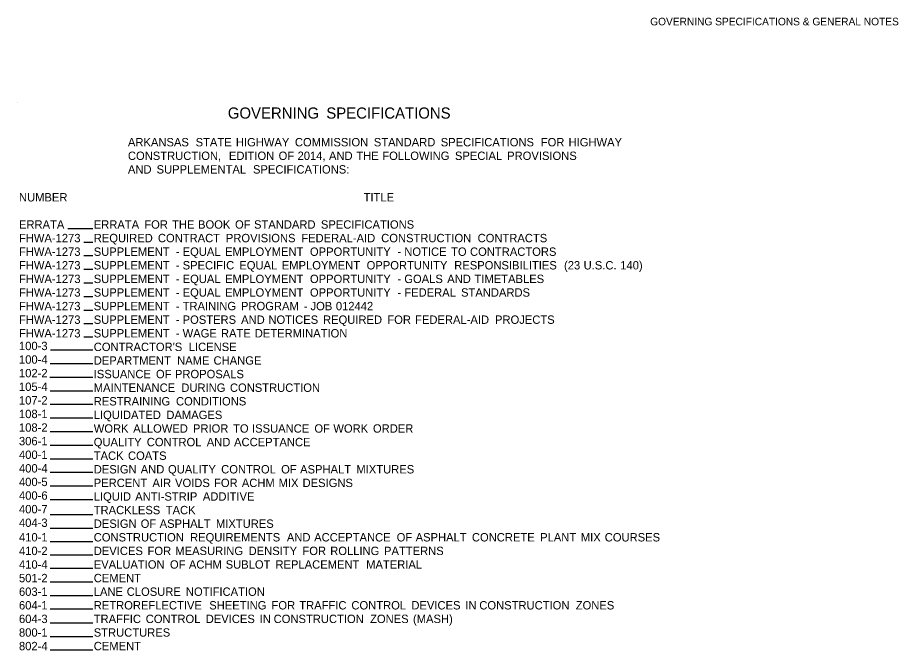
# Model space of a CAD drawing. Extents: x 1930579 to 1932219, y 596452 to 599493.
# Drawn here: x 1931524 to 1932219, y 598994 to 599493 of the extents above; entities that cross this region are included whole.
import ezdxf

# ---------------------------------------------------------------- set-up
doc = ezdxf.new("R2010")
doc.units = 0
for name, color, linetype in [('Default', 7, 'Continuous'), ('R_Border', 7, 'Continuous'), ('R_Border Prem', 7, 'Continuous')]:
    doc.layers.add(name, color=color, linetype=linetype)

msp = doc.modelspace()

# ---------------------------------------------------------------- linework, layer by layer
at = {"layer": 'R_Border'}
for p, q in [((1931524.27, 599426.12), (1931524.27, 599426.12)), ((1931563.85, 599326.81), (1931583.71, 599326.81)), ((1931576.5, 599316.09), (1931583.71, 599316.09)), ((1931576.5, 599305.36), (1931583.71, 599305.36)), ((1931576.5, 599294.64), (1931583.71, 599294.64)), ((1931576.5, 599283.91), (1931583.71, 599283.91)), ((1931576.5, 599273.19), (1931583.71, 599273.19)), ((1931576.5, 599262.46), (1931583.71, 599262.46)), ((1931576.5, 599251.74), (1931583.71, 599251.74)), ((1931576.5, 599241.27), (1931583.53, 599241.27)), ((1931550.12, 599231.03), (1931583.53, 599231.03)), ((1931549.9, 599220.3), (1931583.53, 599220.3)), ((1931549.66, 599209.58), (1931583.53, 599209.58)), ((1931549.9, 599198.85), (1931583.53, 599198.85)), ((1931549.9, 599188.13), (1931583.53, 599188.13)), ((1931549.9, 599177.4), (1931583.53, 599177.4)), ((1931549.9, 599166.68), (1931583.53, 599166.68)), ((1931549.9, 599155.95), (1931583.53, 599155.95)), ((1931549.9, 599145.23), (1931583.53, 599145.23)), ((1931549.9, 599134.5), (1931583.53, 599134.5)), ((1931549.9, 599123.78), (1931583.53, 599123.78)), ((1931549.9, 599113.05), (1931583.53, 599113.05)), ((1931549.9, 599101.16), (1931583.53, 599101.16)), ((1931549.9, 599090.53), (1931583.53, 599090.53)), ((1931549.9, 599079.9), (1931583.53, 599079.9)), ((1931549.9, 599069.37), (1931583.53, 599069.37)), ((1931549.9, 599058.93), (1931583.53, 599058.93)), ((1931549.9, 599048.11), (1931583.53, 599048.11)), ((1931549.9, 599037.2), (1931583.53, 599037.2)), ((1931549.9, 599026.76), (1931583.53, 599026.76)), ((1931549.9, 599015.75), (1931583.53, 599015.75)), ((1931549.9, 599005.12), (1931583.53, 599005.12)), ((1931549.9, 598994.4), (1931583.53, 598994.4))]:
    msp.add_line(p, q, dxfattribs=at)

# ---------------------------------------------------------------- texts
at = {"layer": 'Default'}
for s, height, p in [('GOVERNING', 8.8, (1931690.13, 599413.4)), (' SPECIFICATIONS', 8.8, (1931764.54, 599413.4)), ('           ARKANSAS', 6.6, (1931584.33, 599391.51)), (' STATE', 6.6, (1931662.24, 599391.51)), (' HIGHWAY', 6.6, (1931694.04, 599391.51)), (' COMMISSION', 6.6, (1931740.59, 599391.51)), (' STANDARD', 6.6, (1931802.85, 599391.51)), (' SPECIFICATIONS', 6.6, (1931855.65, 599391.51)), (' FOR', 6.6, (1931934.59, 599391.51)), (' HIGHWAY', 6.6, (1931956.5, 599391.51)), ('           CONSTRUCTION,', 6.6, (1931584.33, 599380.79)), (' EDITION', 6.6, (1931688.52, 599380.79)), (' OF', 6.6, (1931727.73, 599380.79)), (' 2014,', 6.6, (1931742.68, 599380.79)), (' AND', 6.6, (1931767.48, 599380.79)), (' THE', 6.6, (1931789.02, 599380.79)), (' FOLLOWING', 6.6, (1931809.54, 599380.79)), (' SPECIAL', 6.6, (1931866.85, 599380.79)), (' PROVISIONS', 6.6, (1931908.04, 599380.79)), ('           AND', 6.6, (1931584.33, 599370.06)), (' SUPPLEMENTAL', 6.6, (1931631.47, 599370.06)), (' SPECIFICATIONS:', 6.6, (1931707.51, 599370.06)), ('NUMBER', 6.6, (1931525.34, 599348.07)), ('TITLE', 6.6, (1931797.24, 599348.07)), ('ERRATA', 6.6, (1931525.34, 599326.62)), ('ERRATA', 6.6, (1931584.33, 599326.62)), (' FOR', 6.6, (1931621.75, 599326.62)), (' THE', 6.6, (1931643.66, 599326.62)), (' BOOK', 6.6, (1931664.17, 599326.62)), (' OF', 6.6, (1931693.36, 599326.62)), (' STANDARD', 6.6, (1931708.31, 599326.62)), (' SPECIFICATIONS', 6.6, (1931761.11, 599326.62)), ('FHWA-1273', 6.6, (1931525.34, 599315.9)), ('REQUIRED', 6.6, (1931584.33, 599315.9)), (' CONTRACT', 6.6, (1931632.51, 599315.9)), (' PROVISIONS', 6.6, (1931686.12, 599315.9)), (' FEDERAL-AID', 6.6, (1931745.6, 599315.9)), (' CONSTRUCTION', 6.6, (1931808.65, 599315.9)), (' CONTRACTS', 6.6, (1931884.74, 599315.9)), ('FHWA-1273', 6.6, (1931525.34, 599305.17)), ('SUPPLEMENT', 6.6, (1931584.33, 599305.17)), (' EQUAL', 6.6, (1931652.01, 599305.17)), (' EMPLOYMENT', 6.6, (1931685.51, 599305.17)), (' OPPORTUNITY', 6.6, (1931752.45, 599305.17)), (' NOTICE', 6.6, (1931826.89, 599305.17)), (' TO', 6.6, (1931863.8, 599305.17)), (' CONTRACTORS', 6.6, (1931878.76, 599305.17)), (' -', 6.6, (1931646.66, 599305.17)), (' -', 6.6, (1931821.55, 599305.17)), ('FHWA-1273', 6.6, (1931525.34, 599294.45)), ('SUPPLEMENT', 6.6, (1931584.33, 599294.45)), (' -', 6.6, (1931646.66, 599294.45)), (' SPECIFIC', 6.6, (1931652.01, 599294.45)), (' EQUAL', 6.6, (1931696.73, 599294.45)), (' EMPLOYMENT', 6.6, (1931730.23, 599294.45)), (' OPPORTUNITY', 6.6, (1931797.17, 599294.45)), (' RESPONSIBILITIES', 6.6, (1931866.28, 599294.45)), (' (23', 6.6, (1931952.92, 599294.45)), (' U.S.C.', 6.6, (1931968.38, 599294.45)), (' 140)', 6.6, (1931997.29, 599294.45)), ('FHWA-1273', 6.6, (1931525.34, 599283.72)), ('SUPPLEMENT', 6.6, (1931584.33, 599283.72)), (' EQUAL', 6.6, (1931652.01, 599283.72)), (' EMPLOYMENT', 6.6, (1931685.51, 599283.72)), (' OPPORTUNITY', 6.6, (1931752.45, 599283.72)), (' GOALS', 6.6, (1931826.89, 599283.72)), (' AND', 6.6, (1931860.75, 599283.72)), (' TIMETABLES', 6.6, (1931882.29, 599283.72)), (' -', 6.6, (1931646.66, 599283.72)), (' -', 6.6, (1931821.55, 599283.72)), ('FHWA-1273', 6.6, (1931525.34, 599273)), ('SUPPLEMENT', 6.6, (1931584.33, 599273)), (' -', 6.6, (1931646.66, 599273)), (' EQUAL', 6.6, (1931652.01, 599273)), (' EMPLOYMENT', 6.6, (1931685.51, 599273)), (' OPPORTUNITY', 6.6, (1931752.45, 599273)), (' -', 6.6, (1931821.55, 599273)), (' FEDERAL', 6.6, (1931826.89, 599273)), (' STANDARDS', 6.6, (1931871.66, 599273)), ('FHWA-1273', 6.6, (1931525.34, 599262.27)), ('SUPPLEMENT', 6.6, (1931584.33, 599262.27)), (' TRAINING', 6.6, (1931652.01, 599262.27)), (' PROGRAM', 6.6, (1931698.05, 599262.27)), (' JOB', 6.6, (1931752.91, 599262.27)), (' 012442', 6.6, (1931772.92, 599262.27)), (' -', 6.6, (1931646.66, 599262.27)), (' -', 6.6, (1931747.57, 599262.27)), ('FHWA-1273', 6.6, (1931525.34, 599251.55)), ('SUPPLEMENT', 6.6, (1931584.33, 599251.55)), (' -', 6.6, (1931646.66, 599251.55)), (' POSTERS', 6.6, (1931652.01, 599251.55)), (' AND', 6.6, (1931698.16, 599251.55)), (' NOTICES', 6.6, (1931719.7, 599251.55)), (' REQUIRED', 6.6, (1931762.77, 599251.55)), (' FOR', 6.6, (1931813.52, 599251.55)), (' FEDERAL-AID', 6.6, (1931835.42, 599251.55)), (' PROJECTS', 6.6, (1931898.47, 599251.55)), ('FHWA-1273', 6.6, (1931525.34, 599240.82)), ('SUPPLEMENT', 6.6, (1931584.33, 599240.82)), (' WAGE', 6.6, (1931652.01, 599240.82)), (' RATE', 6.6, (1931682.26, 599240.82)), (' DETERMINATION', 6.6, (1931708.92, 599240.82)), (' -', 6.6, (1931646.66, 599240.82)), ('100-3', 6.6, (1931525.34, 599230.84)), ("CONTRACTOR'S", 6.6, (1931584.33, 599230.1)), (' LICENSE', 6.6, (1931656.83, 599230.1)), ('100-4', 6.6, (1931525.34, 599220.12)), ('DEPARTMENT', 6.6, (1931584.33, 599219.37)), (' NAME', 6.6, (1931647.68, 599219.37)), (' CHANGE', 6.6, (1931676.39, 599219.37)), ('102-2', 6.6, (1931525.34, 599209.39)), ('ISSUANCE', 6.6, (1931584.33, 599208.65)), (' OF', 6.6, (1931630.98, 599208.65)), (' PROPOSALS', 6.6, (1931645.93, 599208.65)), ('105-4', 6.6, (1931525.34, 599198.67)), ('MAINTENANCE', 6.6, (1931584.33, 599197.92)), (' DURING', 6.6, (1931650.96, 599197.92)), (' CONSTRUCTION', 6.6, (1931689.32, 599197.92)), ('107-2', 6.6, (1931525.34, 599187.94)), ('RESTRAINING', 6.6, (1931584.33, 599187.2)), (' CONDITIONS', 6.6, (1931646.78, 599187.2)), ('108-1', 6.6, (1931525.34, 599177.22)), ('LIQUIDATED', 6.6, (1931584.33, 599176.47)), (' DAMAGES', 6.6, (1931639.17, 599176.47)), ('108-2', 6.6, (1931525.34, 599166.49)), ('WORK', 6.6, (1931584.33, 599165.75)), (' ALLOWED', 6.6, (1931613, 599165.75)), (' PRIOR', 6.6, (1931660.16, 599165.75)), (' TO', 6.6, (1931691.8, 599165.75)), (' ISSUANCE', 6.6, (1931706.75, 599165.75)), (' OF', 6.6, (1931755.97, 599165.75)), (' WORK', 6.6, (1931770.92, 599165.75)), (' ORDER', 6.6, (1931802.15, 599165.75)), ('306-1', 6.6, (1931525.34, 599155.77)), ('QUALITY', 6.6, (1931584.33, 599155.02)), (' CONTROL', 6.6, (1931623.72, 599155.02)), (' AND', 6.6, (1931671.04, 599155.02)), (' ACCEPTANCE', 6.6, (1931692.58, 599155.02)), ('400-1', 6.6, (1931525.34, 599145.04)), ('TACK', 6.6, (1931584.33, 599144.3)), (' COATS', 6.6, (1931608.91, 599144.3)), ('400-4', 6.6, (1931525.34, 599134.32)), ('DESIGN', 6.6, (1931584.33, 599133.57)), (' AND', 6.6, (1931618.93, 599133.57)), (' QUALITY', 6.6, (1931640.47, 599133.57)), (' CONTROL', 6.6, (1931682.42, 599133.57)), (' OF', 6.6, (1931729.74, 599133.57)), (' ASPHALT', 6.6, (1931744.69, 599133.57)), (' MIXTURES', 6.6, (1931789.09, 599133.57)), ('400-5', 6.6, (1931525.34, 599123.59)), ('PERCENT', 6.6, (1931584.33, 599122.85)), (' AIR', 6.6, (1931628.21, 599122.85)), (' VOIDS', 6.6, (1931646.02, 599122.85)), (' FOR', 6.6, (1931676.8, 599122.85)), (' ACHM', 6.6, (1931698.7, 599122.85)), (' MIX', 6.6, (1931727.72, 599122.85)), (' DESIGNS', 6.6, (1931746.62, 599122.85)), ('400-6', 6.6, (1931525.34, 599112.87)), ('LIQUID', 6.6, (1931584.33, 599112.12)), (' ANTI-STRIP', 6.6, (1931614.58, 599112.12)), (' ADDITIVE', 6.6, (1931667.97, 599112.12)), ('400-7', 6.6, (1931525.34, 599102.14)), ('TRACKLESS', 6.6, (1931584.33, 599101.4)), (' TACK', 6.6, (1931638.69, 599101.4)), ('404-3', 6.6, (1931525.34, 599091.42)), ('DESIGN', 6.6, (1931584.33, 599090.67)), (' OF', 6.6, (1931618.93, 599090.67)), (' ASPHALT', 6.6, (1931633.88, 599090.67)), (' MIXTURES', 6.6, (1931678.28, 599090.67)), ('410-1', 6.6, (1931525.34, 599079.95)), ('CONSTRUCTION', 6.6, (1931584.33, 599079.95)), (' REQUIREMENTS', 6.6, (1931657.86, 599079.95)), (' AND', 6.6, (1931734.24, 599079.95)), (' ACCEPTANCE', 6.6, (1931755.78, 599079.95)), (' OF', 6.6, (1931820.89, 599079.95)), (' ASPHALT', 6.6, (1931835.83, 599079.95)), (' CONCRETE', 6.6, (1931880.24, 599079.95)), (' PLANT', 6.6, (1931934.06, 599079.95)), (' MIX', 6.6, (1931966.16, 599079.95)), (' COURSES', 6.6, (1931985.05, 599079.95)), ('410-2', 6.6, (1931525.34, 599069.22)), ('DEVICES', 6.6, (1931584.33, 599069.22)), (' FOR', 6.6, (1931624.33, 599069.22)), (' MEASURING', 6.6, (1931646.24, 599069.22)), (' DENSITY', 6.6, (1931704.07, 599069.22)), (' FOR', 6.6, (1931746.53, 599069.22)), (' ROLLING', 6.6, (1931768.44, 599069.22)), (' PATTERNS', 6.6, (1931810.9, 599069.22)), ('410-4', 6.6, (1931525.34, 599058.5)), ('EVALUATION', 6.6, (1931584.33, 599058.5)), (' OF', 6.6, (1931642, 599058.5)), (' ACHM', 6.6, (1931656.94, 599058.5)), (' SUBLOT', 6.6, (1931685.96, 599058.5)), (' REPLACEMENT', 6.6, (1931725.24, 599058.5)), (' MATERIAL', 6.6, (1931796.79, 599058.5)), ('501-2', 6.6, (1931525.34, 599047.77)), ('CEMENT', 6.6, (1931584.33, 599047.77)), ('603-1', 6.6, (1931525.34, 599037.05)), ('LANE', 6.6, (1931584.33, 599037.05)), (' CLOSURE', 6.6, (1931607.92, 599037.05)), (' NOTIFICATION', 6.6, (1931654.58, 599037.05)), ('604-1', 6.6, (1931525.34, 599026.32)), ('RETROREFLECTIVE', 6.6, (1931584.33, 599026.32)), (' SHEETING', 6.6, (1931673, 599026.32)), (' FOR', 6.6, (1931722.13, 599026.32)), (' TRAFFIC', 6.6, (1931744.03, 599026.32)), (' CONTROL', 6.6, (1931785.16, 599026.32)), (' DEVICES', 6.6, (1931832.48, 599026.32)), (' IN', 6.6, (1931875.05, 599026.32)), (' CONSTRUCTION', 6.6, (1931886.08, 599026.32)), (' ZONES', 6.6, (1931962.17, 599026.32)), ('604-3', 6.6, (1931525.34, 599015.6)), ('TRAFFIC', 6.6, (1931584.33, 599015.6)), (' CONTROL', 6.6, (1931622.9, 599015.6)), (' DEVICES', 6.6, (1931670.22, 599015.6)), (' IN', 6.6, (1931712.79, 599015.6)), (' CONSTRUCTION', 6.6, (1931723.81, 599015.6)), (' ZONES', 6.6, (1931799.91, 599015.6)), (' (MASH)', 6.6, (1931833.76, 599015.6)), ('800-1', 6.6, (1931525.34, 599004.87)), ('STRUCTURES', 6.6, (1931584.33, 599004.87)), ('802-4', 6.6, (1931525.34, 598994.15)), ('CEMENT', 6.6, (1931584.33, 598994.15))]:
    msp.add_text(s, height=height, dxfattribs=at).set_placement(p)
at = {"layer": 'R_Border Prem'}
msp.add_text('GOVERNING SPECIFICATIONS & GENERAL NOTES', height=6, rotation=360, dxfattribs=at).set_placement((1932023.37, 599486.95))

doc.saveas('drawing.dxf')
